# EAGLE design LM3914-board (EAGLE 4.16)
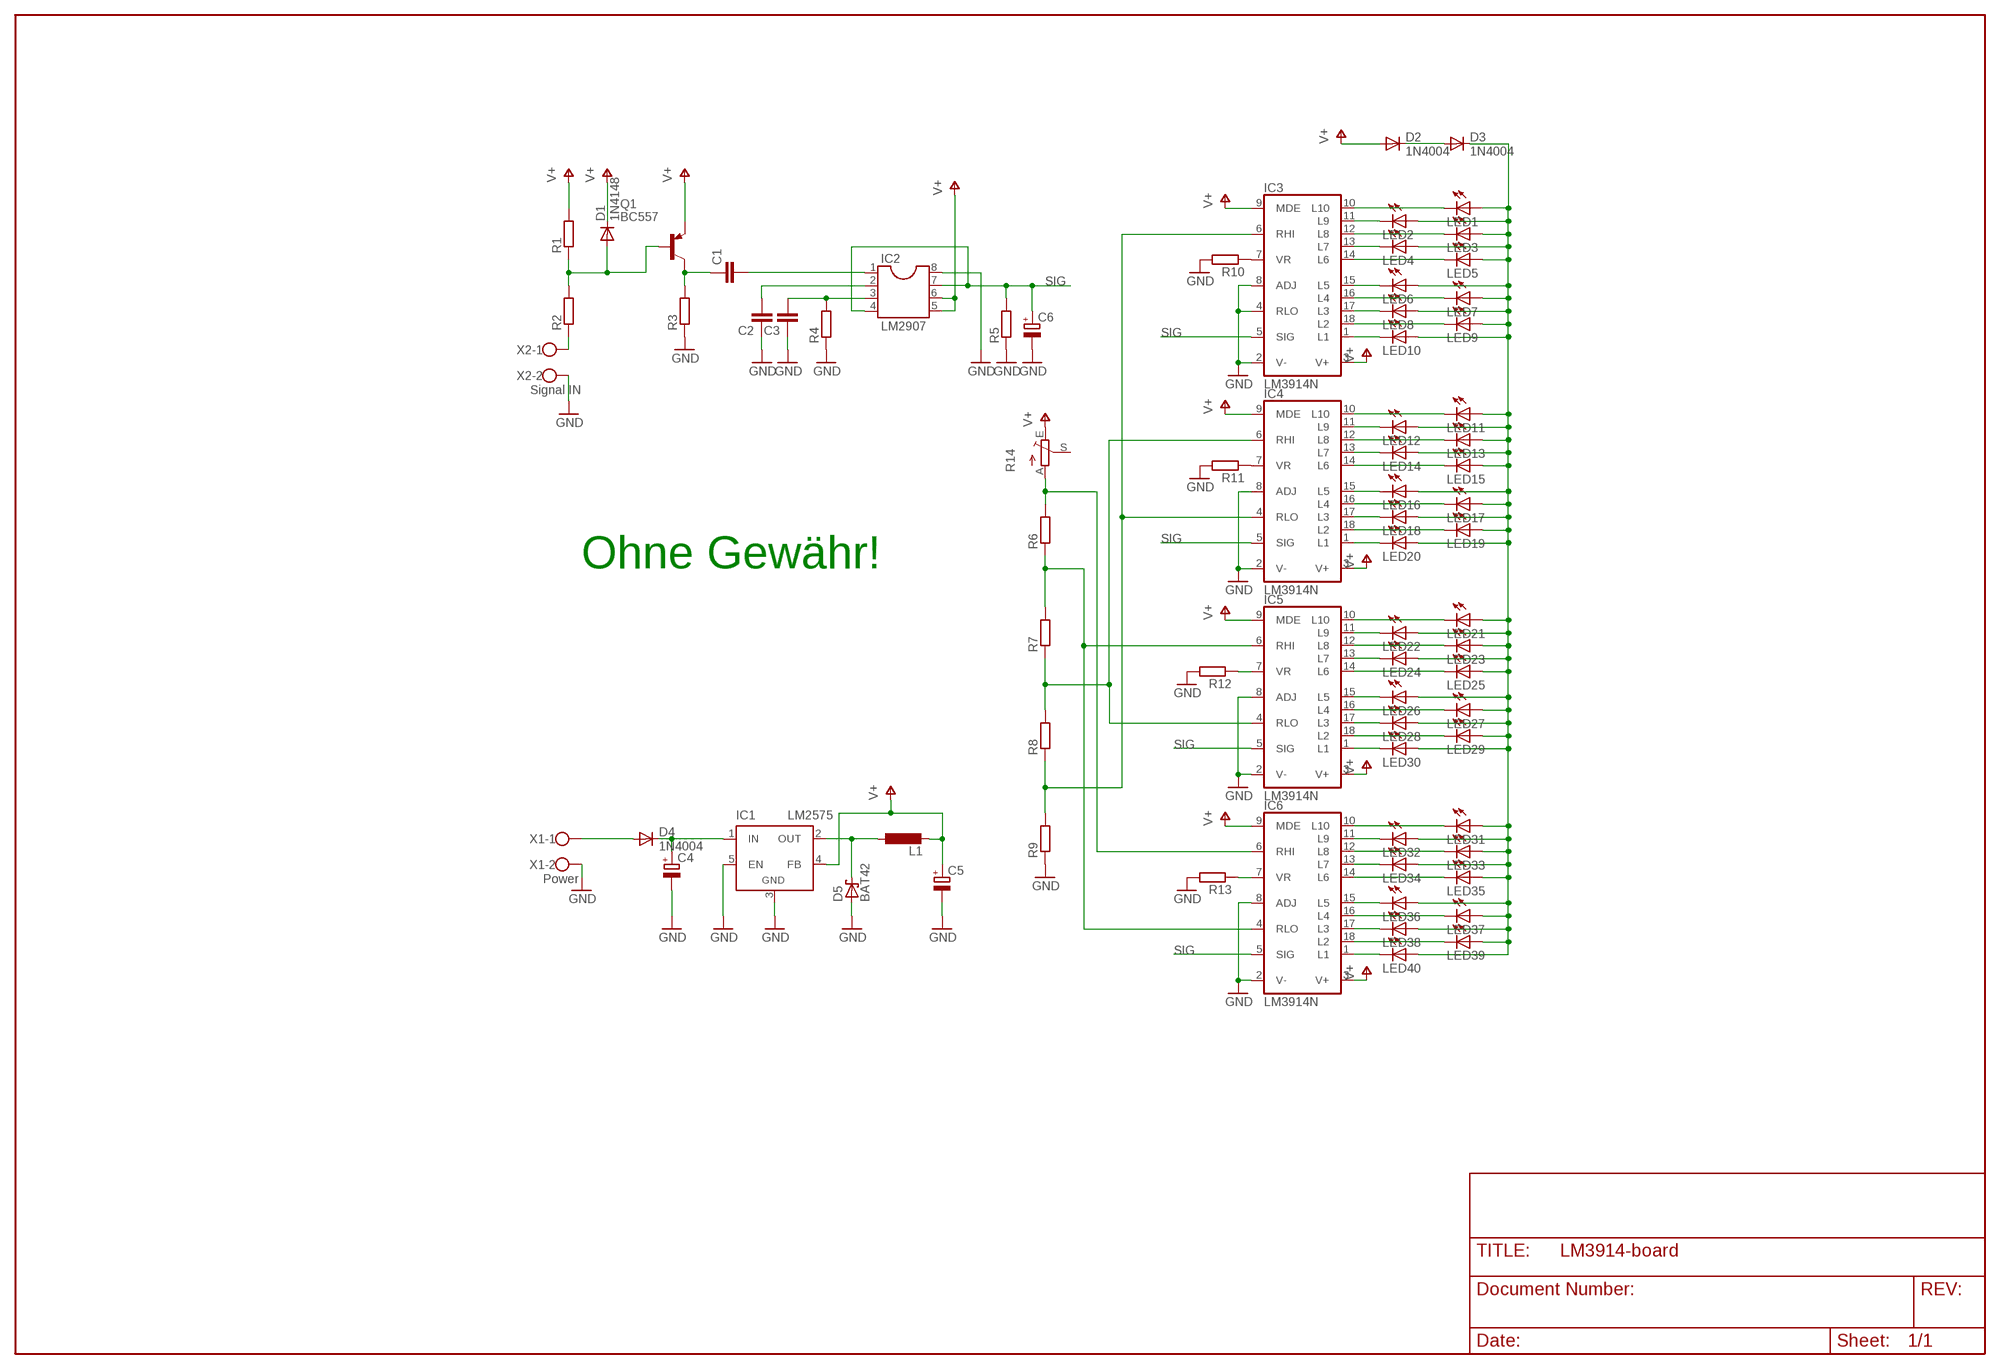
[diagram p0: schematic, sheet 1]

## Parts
C1  C-EU025-024X044  [C025-024X044]
C2  C-EU025-024X044  [C025-024X044]
C3  C-EU025-024X044  [C025-024X044]
C4  CPOL-EUE2.5-7  [E2,5-7]
C5  CPOL-EUE2.5-7  [E2,5-7]
C6  CPOL-EUE2.5-7  [E2,5-7]
D1  1N4148  [DO35-10]
D2  1N4004  [DO41-10]
D3  1N4004  [DO41-10]
D4  1N4004  [DO41-10]
D5  BAT42  [DO35-10]
IC1  LM2575  LM2596TV  [TO220-51]
IC2  LM2907  DIL8  [DIL08]
IC3  LM3914N  [DIL18]
IC4  LM3914N  [DIL18]
IC5  LM3914N  [DIL18]
IC6  LM3914N  [DIL18]
L1  L-EU0207/10  [0207/10]
LED1  LED3MM  [LED3MM]
LED2  LED3MM  [LED3MM]
LED3  LED3MM  [LED3MM]
LED4  LED3MM  [LED3MM]
LED5  LED3MM  [LED3MM]
LED6  LED3MM  [LED3MM]
LED7  LED3MM  [LED3MM]
LED8  LEDSQR2X5  [LED2X5]
LED9  LEDSQR2X5  [LED2X5]
LED10  LEDSQR2X5  [LED2X5]
LED11  LED3MM  [LED3MM]
LED12  LED3MM  [LED3MM]
LED13  LED3MM  [LED3MM]
LED14  LED3MM  [LED3MM]
LED15  LED3MM  [LED3MM]
LED16  LED3MM  [LED3MM]
LED17  LED3MM  [LED3MM]
LED18  LED3MM  [LED3MM]
LED19  LED3MM  [LED3MM]
LED20  LED3MM  [LED3MM]
LED21  LED3MM  [LED3MM]
LED22  LED3MM  [LED3MM]
LED23  LED3MM  [LED3MM]
LED24  LED3MM  [LED3MM]
LED25  LED3MM  [LED3MM]
LED26  LED3MM  [LED3MM]
LED27  LED3MM  [LED3MM]
LED28  LED3MM  [LED3MM]
LED29  LED3MM  [LED3MM]
LED30  LED3MM  [LED3MM]
LED31  LED3MM  [LED3MM]
LED32  LED3MM  [LED3MM]
LED33  LED3MM  [LED3MM]
LED34  LED3MM  [LED3MM]
LED35  LED3MM  [LED3MM]
LED36  LED3MM  [LED3MM]
LED37  LED3MM  [LED3MM]
LED38  LED3MM  [LED3MM]
LED39  LED3MM  [LED3MM]
LED40  LED3MM  [LED3MM]
Q1  BC557  [TO92-EBC]
R1  R-EU_0204/7  [0204/7]
R2  R-EU_0204/7  [0204/7]
R3  R-EU_0204/7  [0204/7]
R4  R-EU_0204/7  [0204/7]
R5  R-EU_0204/7  [0204/7]
R6  R-EU_0204/7  [0204/7]
R7  R-EU_0204/7  [0204/7]
R8  R-EU_0204/7  [0204/7]
R9  R-EU_0204/7  [0204/7]
R10  R-EU_0204/7  [0204/7]
R11  R-EU_0204/7  [0204/7]
R12  R-EU_0204/7  [0204/7]
R13  R-EU_0204/7  [0204/7]
R14  TRIM_EU-LI10  [LI10]
X1  Power  W237-102  [W237-102]
X2  Signal IN  W237-102  [W237-102]

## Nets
GND: C2.1 C3.1 C4.- C5.- C6.- D5.A IC1.3(GND) IC1.5(EN) IC2.8 IC3.2(V-) IC3.4(RLO) IC3.8(ADJ) IC4.2(V-) IC4.8(ADJ) IC5.2(V-) IC5.8(ADJ) IC6.2(V-) IC6.8(ADJ) R3.1 R4.1 R5.1 R9.1 R10.2 R11.2 R12.2 R13.2 X1.2 X2.2
N$1: C4.+ D4.C IC1.1(IN)
N$2: D5.C IC1.2(OUT) L1.1
N$3: IC3.10(L10) LED1.K(C)
N$4: IC3.11(L9) LED2.K(C)
N$5: IC3.12(L8) LED3.K(C)
N$6: IC3.13(L7) LED4.K(C)
N$7: IC3.14(L6) LED5.K(C)
N$8: IC3.16(L4) LED7.K(C)
N$9: IC3.17(L3) LED8.K(C)
N$10: IC3.18(L2) LED9.K(C)
N$11: IC3.1(L1) LED10.K(C)
N$12: IC4.11(L9) LED12.K(C)
N$13: IC4.1(L1) LED20.K(C)
N$14: IC6.10(L10) LED31.K(C)
N$15: IC6.11(L9) LED32.K(C)
N$16: IC6.12(L8) LED33.K(C)
N$17: IC6.13(L7) LED34.K(C)
N$18: IC6.14(L6) LED35.K(C)
N$19: IC6.15(L5) LED36.K(C)
N$20: IC6.16(L4) LED37.K(C)
N$21: IC6.17(L3) LED38.K(C)
N$22: IC6.18(L2) LED39.K(C)
N$23: IC6.1(L1) LED40.K(C)
N$24: IC5.1(L1) LED30.K(C)
N$25: IC4.18(L2) LED19.K(C)
N$26: IC4.12(L8) LED13.K(C)
N$27: IC4.13(L7) LED14.K(C)
N$28: IC4.14(L6) LED15.K(C)
N$29: IC4.15(L5) LED16.K(C)
N$30: IC4.16(L4) LED17.K(C)
N$31: IC4.17(L3) LED18.K(C)
N$32: IC5.12(L8) LED23.K(C)
N$33: IC4.10(L10) LED11.K(C)
N$34: IC5.10(L10) LED21.K(C)
N$35: IC5.13(L7) LED24.K(C)
N$36: IC5.14(L6) LED25.K(C)
N$37: IC3.15(L5) LED6.K(C)
N$38: IC5.18(L2) LED29.K(C)
N$39: IC5.15(L5) LED26.K(C)
N$40: IC5.16(L4) LED27.K(C)
N$41: IC5.17(L3) LED28.K(C)
N$42: IC5.11(L9) LED22.K(C)
N$43: D3.C LED1.A LED2.A LED3.A LED4.A LED5.A LED6.A LED7.A LED8.A LED9.A LED10.A LED11.A LED12.A LED13.A LED14.A LED15.A LED16.A LED17.A LED18.A LED19.A LED20.A LED21.A LED22.A LED23.A LED24.A LED25.A LED26.A LED27.A LED28.A LED29.A LED30.A LED31.A LED32.A LED33.A LED34.A LED35.A LED36.A LED37.A LED38.A LED39.A LED40.A
N$44: IC6.7(VR) R13.1
N$45: D2.C D3.A
N$46: IC5.7(VR) R12.1
N$47: IC4.7(VR) R11.1
N$48: IC3.7(VR) R10.1
N$49: D1.A Q1.B R1.1 R2.2
N$50: C1.1 Q1.C R3.2
N$51: C1.2 IC2.1
N$52: C2.2 IC2.2
N$53: C3.2 IC2.3 R4.2
N$54: IC5.6(RHI) IC6.4(RLO) R6.1 R7.2
N$55: IC4.6(RHI) IC5.4(RLO) R7.1 R8.2
N$56: IC3.6(RHI) IC4.4(RLO) R8.1 R9.2
N$57: IC6.6(RHI) R6.2 R14.A
N$58: R2.1 X2.1
N$59: D4.A X1.1
SIG: C6.+ IC2.4 IC2.7 IC3.5(SIG) IC4.5(SIG) IC5.5(SIG) IC6.5(SIG) R5.2
V+: C5.+ D1.C D2.A IC1.4(FB) IC2.5 IC2.6 IC3.3(V+) IC3.9(MDE) IC4.3(V+) IC4.9(MDE) IC5.3(V+) IC5.9(MDE) IC6.3(V+) IC6.9(MDE) L1.2 Q1.E R1.2 R14.E
Unconnected: R14.S

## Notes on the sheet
- Ohne Gewähr!

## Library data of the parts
C1-C3 = rcl:C-EU: CAPACITOR, European symbol
C4-C6 = rcl:CPOL-EU: POLARIZED CAPACITOR, European symbol
D1 = diode:1N4148: DIODE
D2-D4 = diode:1N4004: DIODE
D5 = diode:BAT42: DIODE
IC1 = linear:LM2596T: STEP-DOWN VOLTAGE REGULATOR
IC2 = ic-package:DIL8: Dual In Line
IC3-IC6 = linear:LM3914N: LED DRIVER senses analog voltage levels and drives 10 LEDs
L1 = rcl:L-EU: INDUCTOR, European symbol
LED1-LED40 = led:LED: LED
Q1 = transistor-pnp:BC557*: PNP Transistror
R1-R13 = rcl:R-EU_: RESISTOR, European symbol
R14 = pot:TRIM_EU-: POTENTIOMETER
X1 X2 = con-wago-500:W237-102: WAGO SCREW CLAMP

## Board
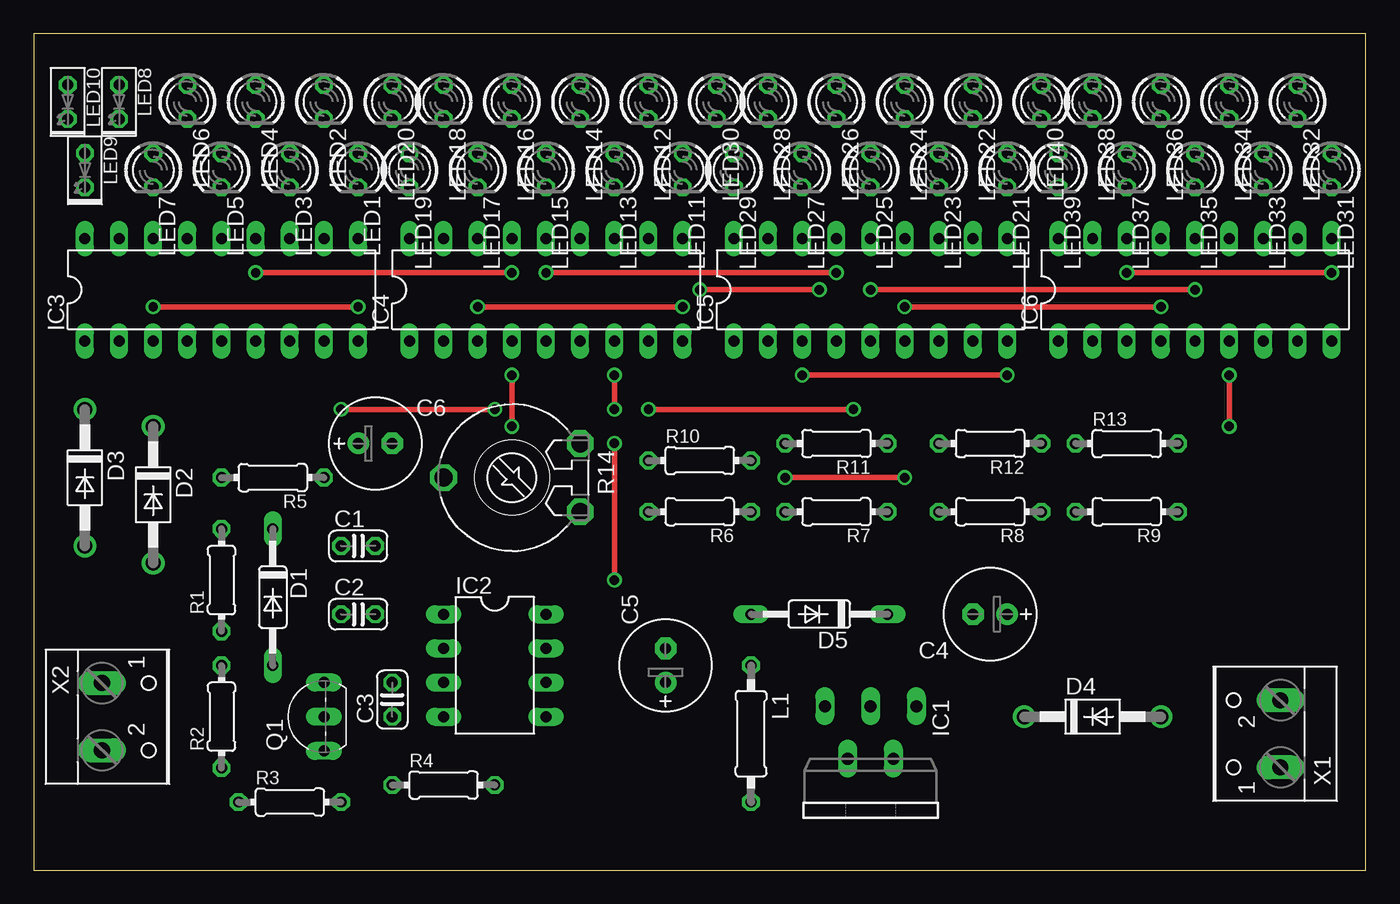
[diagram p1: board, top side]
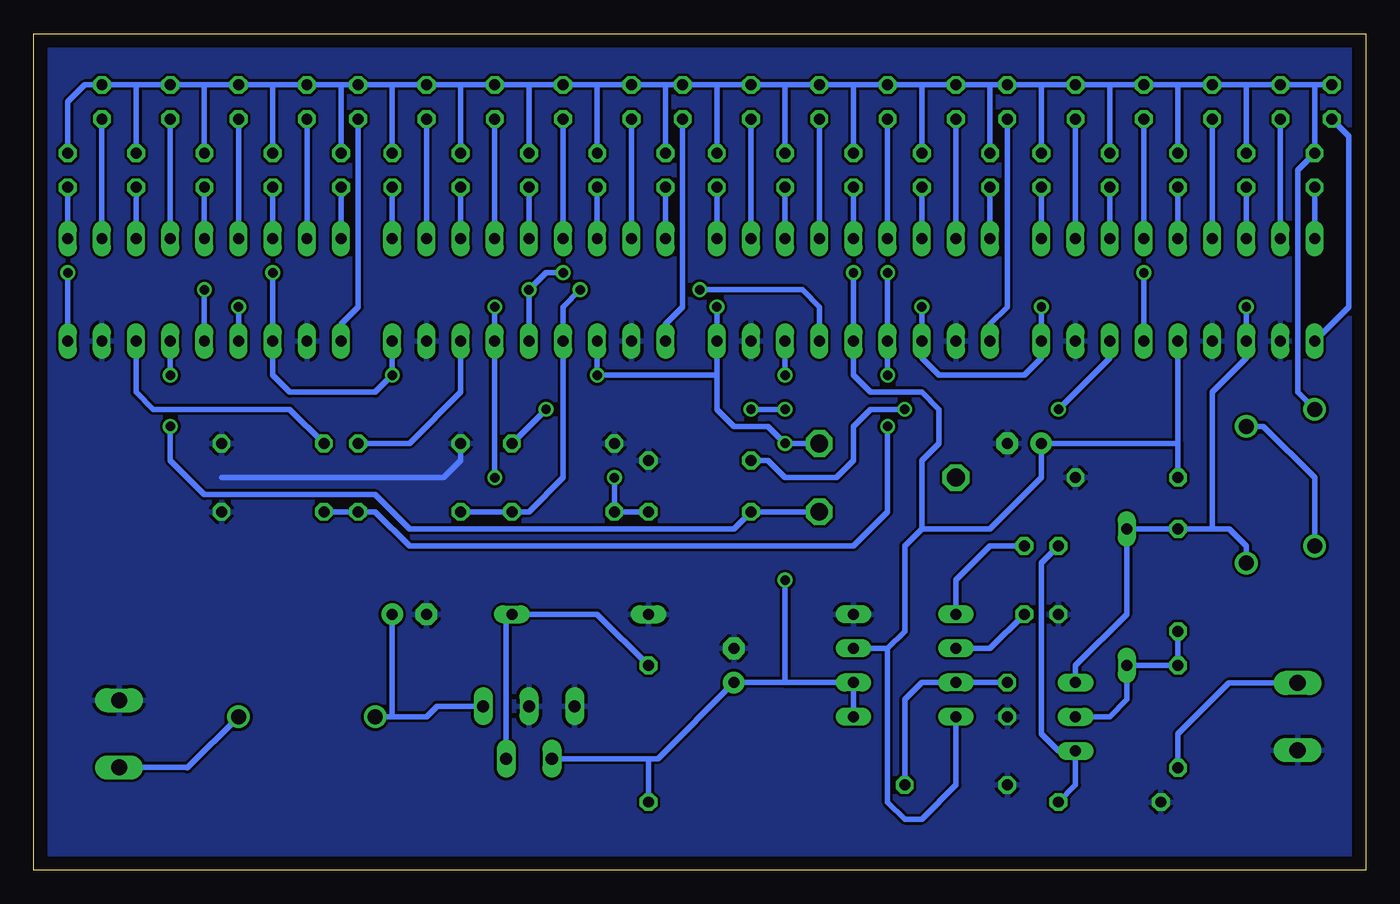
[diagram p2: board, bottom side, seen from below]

Size 99.06 x 62.23 mm. Coordinates in mm from the lower left corner, seen from the top.
Outline: 99.06,0 99.06,62.23 0,62.23 0,0 99.06,0
Copper layers (1*16): Top 0.035mm / dielectric 1.5mm / Bottom 0.035mm
Design rules "default": minimum track width 10mil, minimum drill 24mil, track to track 8mil, track to pad 8mil, pad to pad 8mil, via to via 8mil, smd to smd 8mil, copper to edge 40mil, drill to drill 8mil, minimum pad ring 10mil, minimum via ring 8mil, stop-mask expansion 4mil, vias tented up to drill 0mil, thermal gap 10mil

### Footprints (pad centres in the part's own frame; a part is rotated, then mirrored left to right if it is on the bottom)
C025-024X044 = drill 0.813 octagon: 1 -1.27,0; 2 1.27,0
E2,5-7 = drill 0.813 pad 1.6 round: + -1.27,0 | drill 0.813 pad 1.6 octagon: - 1.27,0
DO35-10 = drill 0.813 long: A 5.08,0; C -5.08,0
DO41-10 = drill 1.118 round: A 5.08,0; C -5.08,0
TO220-51 = drill 0.9 long: 1 -3.4,-8.4; 2 -1.7,-4.5; 3 0,-8.4; 4 1.7,-4.5; 5 3.4,-8.4
DIL08 = drill 0.813 long: 1 -3.81,-3.81; 2 -1.27,-3.81; 3 1.27,-3.81; 4 3.81,-3.81; 5 3.81,3.81; 6 1.27,3.81; 7 -1.27,3.81; 8 -3.81,3.81
DIL18 = drill 0.813 long: 1 -10.16,-3.81; 2 -7.62,-3.81; 3 -5.08,-3.81; 4 -2.54,-3.81; 5 0,-3.81; 6 2.54,-3.81; 7 5.08,-3.81; 8 7.62,-3.81; 9 10.16,-3.81; 10 10.16,3.81; 11 7.62,3.81; 12 5.08,3.81; 13 2.54,3.81; 14 0,3.81; 15 -2.54,3.81; 16 -5.08,3.81; 17 -7.62,3.81; 18 -10.16,3.81
0207/10 = drill 0.813 octagon: 1 -5.08,0; 2 5.08,0
LED3MM = drill 0.813 octagon: A -1.27,0; K 1.27,0
LED2X5 = drill 0.813 octagon: A -1.27,0; K 1.27,0
TO92-EBC = drill 0.813 long: B 0,-1.27; C -2.54,-1.27; E 2.54,-1.27
0204/7 = drill 0.813 octagon: 1 -3.81,0; 2 3.81,0
LI10 = drill 1.321 octagon: A -2.54,-5.08; E 2.54,-5.08; S 0,5.08
W237-102 = drill 1.194 long: 1 -2.5,-1.27; 2 2.5,-1.27

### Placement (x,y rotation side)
C1  24.13,24.13 0 top
C2  24.13,19.05 0 top
C3  26.67,12.7 90 top
C4  71.12,19.05 180 top
C5  46.99,15.24 90 top
C6  25.4,31.75 0 top
D1  17.78,20.32 270 top
D2  8.89,27.94 270 top
D3  3.81,29.21 270 top
D4  78.74,11.43 0 top
D5  58.42,19.05 180 top
IC1  62.23,3.81 180 top
IC2  34.29,15.24 270 top
IC3  13.97,43.18 0 top
IC4  38.1,43.18 0 top
IC5  62.23,43.18 0 top
IC6  86.36,43.18 0 top
L1  53.34,10.16 270 top
LED1  24.13,52.07 270 top
LED2  21.59,57.15 270 top
LED3  19.05,52.07 270 top
LED4  16.51,57.15 270 top
LED5  13.97,52.07 270 top
LED6  11.43,57.15 270 top
LED7  8.89,52.07 270 top
LED8  6.35,57.15 270 top
LED9  3.81,52.07 270 top
LED10  2.54,57.15 270 top
LED11  48.26,52.07 270 top
LED12  45.72,57.15 270 top
LED13  43.18,52.07 270 top
LED14  40.64,57.15 270 top
LED15  38.1,52.07 270 top
LED16  35.56,57.15 270 top
LED17  33.02,52.07 270 top
LED18  30.48,57.15 270 top
LED19  27.94,52.07 270 top
LED20  26.67,57.15 270 top
LED21  72.39,52.07 270 top
LED22  69.85,57.15 270 top
LED23  67.31,52.07 270 top
LED24  64.77,57.15 270 top
LED25  62.23,52.07 270 top
LED26  59.69,57.15 270 top
LED27  57.15,52.07 270 top
LED28  54.61,57.15 270 top
LED29  52.07,52.07 270 top
LED30  50.8,57.15 270 top
LED31  96.52,52.07 270 top
LED32  93.98,57.15 270 top
LED33  91.44,52.07 270 top
LED34  88.9,57.15 270 top
LED35  86.36,52.07 270 top
LED36  83.82,57.15 270 top
LED37  81.28,52.07 270 top
LED38  78.74,57.15 270 top
LED39  76.2,52.07 270 top
LED40  74.93,57.15 270 top
Q1  20.32,11.43 90 top
R1  13.97,21.59 90 top
R2  13.97,11.43 90 top
R3  19.05,5.08 0 top
R4  30.48,6.35 0 top
R5  17.78,29.21 180 top
R6  49.53,26.67 180 top
R7  59.69,26.67 180 top
R8  71.12,26.67 180 top
R9  81.28,26.67 180 top
R10  49.53,30.48 0 top
R11  59.69,31.75 180 top
R12  71.12,31.75 180 top
R13  81.28,31.75 0 top
R14  35.56,29.21 90 top
X1  91.44,10.16 90 top
X2  6.35,11.43 270 top

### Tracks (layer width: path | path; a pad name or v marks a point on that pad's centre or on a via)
GND
  Bottom 0.406: R12.2 67.31,30.48 68.58,29.21 85.09,29.21
  pour Bottom: 0,62.23 0,0 99.06,0 99.06,62.23
N$1
  Bottom 0.406: IC1.1 69.07,12.21 69.85,11.43 72.39,11.43 | 72.39,11.43 D4.C | 72.39,11.43 C4.+
N$2
  Bottom 0.406: IC1.2 63.93,18.62 D5.C 57.15,19.05 L1.1
N$3
  Bottom 0.406: IC3.10 LED1.K
N$4
  Bottom 0.406: IC3.11 LED2.K
N$5
  Bottom 0.406: IC3.12 LED3.K
N$6
  Bottom 0.406: IC3.13 LED4.K
N$7
  Bottom 0.406: IC3.14 LED5.K
N$8
  Bottom 0.406: IC3.16 LED7.K
N$9
  Bottom 0.406: IC3.17 LED8.K
N$10
  Bottom 0.406: IC3.18 LED9.K
N$11
  Bottom 0.406: LED10.K 1.27,54.61 1.27,41.91 IC3.1
N$12
  Bottom 0.406: IC4.11 LED12.K
N$13
  Bottom 0.406: LED20.K 26.67,41.91 27.94,40.64 IC4.1
N$14
  Bottom 0.406: IC6.10 LED31.K
N$15
  Bottom 0.406: IC6.11 LED32.K
N$16
  Bottom 0.406: IC6.12 LED33.K
N$17
  Bottom 0.406: IC6.13 LED34.K
N$18
  Bottom 0.406: IC6.14 LED35.K
N$19
  Bottom 0.406: IC6.15 LED36.K
N$20
  Bottom 0.406: IC6.16 LED37.K
N$21
  Bottom 0.406: IC6.17 LED38.K
N$22
  Bottom 0.406: IC6.18 LED39.K
N$23
  Bottom 0.406: LED40.K 74.93,41.91 76.2,40.64 IC6.1
N$24
  Bottom 0.406: LED30.K 50.8,41.91 52.07,40.64 IC5.1
N$25
  Bottom 0.406: IC4.18 LED19.K
N$26
  Bottom 0.406: IC4.12 LED13.K
N$27
  Bottom 0.406: IC4.13 LED14.K
N$28
  Bottom 0.406: IC4.14 LED15.K
N$29
  Bottom 0.406: IC4.15 LED16.K
N$30
  Bottom 0.406: IC4.16 LED17.K
N$31
  Bottom 0.406: IC4.17 LED18.K
N$32
  Bottom 0.406: IC5.12 LED23.K
N$33
  Bottom 0.406: IC4.10 LED11.K
N$34
  Bottom 0.406: IC5.10 LED21.K
N$35
  Bottom 0.406: IC5.13 LED24.K
N$36
  Bottom 0.406: IC5.14 LED25.K
N$37
  Bottom 0.406: IC3.15 LED6.K
N$38
  Bottom 0.406: IC5.18 LED29.K
N$39
  Bottom 0.406: IC5.15 LED26.K
N$40
  Bottom 0.406: IC5.16 LED27.K
N$41
  Bottom 0.406: IC5.17 LED28.K
N$42
  Bottom 0.406: IC5.11 LED22.K
N$43
  Bottom 0.406: 8.89,58.42 LED8.A LED10.A 3.81,58.42 LED9.A 5.08,52.07 5.08,35.56 D3.C | 8.89,58.42 LED6.A 13.97,58.42 | 13.97,58.42 LED4.A 19.05,58.42 | 19.05,58.42 LED2.A 24.13,58.42 | 24.13,58.42 LED20.A 27.94,58.42 | 27.94,58.42 LED18.A 33.02,58.42 | 33.02,58.42 LED16.A 38.1,58.42 | 38.1,58.42 LED14.A 43.18,58.42 | 43.18,58.42 LED12.A 48.26,58.42 | 48.26,58.42 LED30.A 52.07,58.42 | 52.07,58.42 LED28.A 57.15,58.42 | 8.89,58.42 LED7.A | 13.97,58.42 LED5.A | 19.05,58.42 LED3.A | 24.13,58.42 LED1.A | 27.94,58.42 LED19.A | 33.02,58.42 LED17.A | 38.1,58.42 LED15.A | 43.18,58.42 LED13.A | 48.26,58.42 LED11.A | 52.07,58.42 LED29.A | 57.15,58.42 LED26.A 62.23,58.42 | 62.23,58.42 LED24.A 67.31,58.42 | 67.31,58.42 LED22.A 72.39,58.42 | 72.39,58.42 LED40.A 76.2,58.42 | 76.2,58.42 LED38.A 81.28,58.42 | 81.28,58.42 LED36.A 86.36,58.42 | 81.28,58.42 LED37.A | 76.2,58.42 LED39.A | 72.39,58.42 LED21.A | 67.31,58.42 LED23.A | 62.23,58.42 LED25.A | 57.15,58.42 LED27.A | 86.36,58.42 LED34.A 91.44,58.42 | 91.44,58.42 LED32.A 95.25,58.42 96.52,57.15 LED31.A | 91.44,58.42 LED33.A | 86.36,58.42 LED35.A
N$44
  Bottom 0.406: IC6.7 91.44,35.56 90.17,34.29 80.01,34.29 R13.1
N$45
  Bottom 0.406: D2.C 7.62,33.02 3.81,29.21 D3.A
N$46
  Bottom 0.406: IC5.7 67.31,35.56 71.12,31.75 R12.1
N$47  (via drill 0.7)
  Top 0.406: v45.72,34.29 v60.96,34.29 | v43.18,34.29 v43.18,36.83
  Bottom 0.406: v60.96,34.29 R11.1 | v43.18,34.29 v45.72,34.29 | v43.18,36.83 IC4.7
N$48  (via drill 0.7)
  Top 0.406: v22.86,34.29 v34.29,34.29
  Bottom 0.406: IC3.7 19.05,38.1 v22.86,34.29 | R10.1 44.45,30.48 43.18,29.21 39.37,29.21 38.1,30.48 38.1,33.02 36.83,34.29 v34.29,34.29
N$49
  Bottom 0.406: Q1.B 19.05,11.43 17.78,12.7 D1.A R2.2 R1.1
N$50
  Bottom 0.406: R3.2 21.59,6.35 Q1.C 22.86,8.89 24.13,10.16 24.13,22.86 C1.1
N$51
  Bottom 0.406: C1.2 27.94,24.13 30.48,21.59 IC2.1
N$52
  Bottom 0.406: IC2.2 27.94,16.51 C2.2
N$53
  Bottom 0.406: C3.2 IC2.3 33.02,13.97 34.29,12.7 R4.2
N$54  (via drill 0.7)
  Top 0.406: v64.77,41.91 v83.82,41.91 | v55.88,29.21 v64.77,29.21
  Bottom 0.406: v83.82,41.91 IC6.4 | v64.77,41.91 IC5.6 v64.77,29.21 | R6.1 R7.2 v55.88,29.21
N$55  (via drill 0.7)
  Top 0.406: v49.53,43.18 v58.42,43.18
  Bottom 0.406: R8.2 R7.1 62.23,26.67 59.69,29.21 IC5.4 59.69,41.91 v58.42,43.18 | IC4.6 40.64,41.91 41.91,43.18 v49.53,43.18
N$56  (via drill 0.7)
  Top 0.406: v16.51,44.45 v35.56,44.45 | v35.56,36.83 v35.56,33.02
  Bottom 0.406: R9.2 R8.1 73.66,26.67 71.12,24.13 38.1,24.13 35.56,26.67 v35.56,33.02 | IC3.6 v16.51,44.45 | v35.56,44.45 IC4.4 v35.56,36.83
N$57  (via drill 0.7)
  Top 0.406: v88.9,33.02 v88.9,36.83
  Bottom 0.406: R14.A R6.2 46.99,25.4 71.12,25.4 73.66,27.94 86.36,27.94 88.9,30.48 v88.9,33.02 | v88.9,36.83 IC6.6
N$58
  Bottom 0.406: X2.1 10.2,13.93 13.97,10.16 R2.1
N$59
  Bottom 0.406: X1.1 87.67,7.66 87.63,7.62 D4.A
SIG  (via drill 0.7)
  Top 0.406: v62.23,43.18 v86.36,43.18 | v38.1,44.45 v59.69,44.45
  Bottom 0.406: 35.56,16.51 IC2.7 | 35.56,16.51 34.29,17.78 34.29,24.13 33.02,25.4 | 33.02,25.4 27.94,25.4 24.13,29.21 C6.+ 13.97,31.75 | 13.97,31.75 R5.2 | IC2.4 30.48,6.35 33.02,3.81 34.29,3.81 35.56,5.08 35.56,16.51 | 13.97,31.75 IC3.5 | v86.36,43.18 IC6.5 | IC5.5 v62.23,43.18 60.96,44.45 v59.69,44.45 | v38.1,44.45 IC4.5 38.1,36.83 36.83,35.56 33.02,35.56 31.75,34.29 31.75,31.75 33.02,30.48 33.02,25.4
V+  (via drill 0.7)
  Top 0.406: v81.28,44.45 v96.52,44.45 | v8.89,41.91 v24.13,41.91 | v33.02,41.91 v48.26,41.91 | v57.15,36.83 v72.39,36.83 | v43.18,31.75 v43.18,21.59
  Bottom 0.406: v96.52,44.45 IC6.9 | v81.28,44.45 IC6.3 81.28,36.83 80.01,35.56 73.66,35.56 v72.39,36.83 | 53.34,8.31 52.65,8.31 C5.+ 43.18,13.97 | 53.34,8.31 IC1.4 | 53.34,8.31 L1.2 | IC2.5 IC2.6 43.18,13.97 | D2.A 8.89,24.13 10.16,25.4 11.43,25.4 | 11.43,25.4 R1.2 D1.C 17.78,19.05 21.59,15.24 Q1.E | 11.43,25.4 11.43,35.56 8.89,38.1 IC3.3 v8.89,41.91 | v24.13,41.91 IC3.9 24.13,38.1 25.4,36.83 31.75,36.83 33.02,38.1 IC4.3 v33.02,41.91 | v48.26,41.91 IC4.9 48.26,36.83 | v72.39,36.83 IC5.9 v72.39,36.83 | 48.26,36.83 v57.15,36.83 IC5.3 | R14.E v43.18,31.75 44.45,33.02 46.99,33.02 48.26,34.29 48.26,36.83 | v43.18,21.59 43.18,13.97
